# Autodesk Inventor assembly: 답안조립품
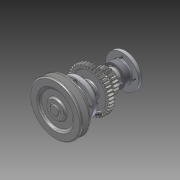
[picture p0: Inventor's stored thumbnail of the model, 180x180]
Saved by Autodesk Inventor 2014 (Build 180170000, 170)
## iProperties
Created: 2016-01
Part Number: 답안조립품
Document SubType Name: Assembly
Designer: SCD-A15
Author: SCD-A15
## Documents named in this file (16)
- C:\Users\SCD-A15\Desktop\460105V1033\답안조립품.iam
- C:\Users\SCD-A15\Desktop\460105V1033\V-벨트풀리.ipt
- C:\Users\SCD-A15\Desktop\460105V1033\뒤커버.ipt
- C:\Users\SCD-A15\Desktop\460105V1033\멈춤나사 - M4x10.ipt
- C:\Users\SCD-A15\Desktop\460105V1033\베어링 6203.ipt
- C:\Users\SCD-A15\Desktop\460105V1033\본체.ipt
- C:\Users\SCD-A15\Desktop\460105V1033\볼트 M3 x 8.ipt
- C:\Users\SCD-A15\Desktop\460105V1033\볼트 M3 x 10.ipt
- C:\Users\SCD-A15\Desktop\460105V1033\부시1.ipt
- C:\Users\SCD-A15\Desktop\460105V1033\부시2.ipt
- C:\Users\SCD-A15\Desktop\460105V1033\스퍼기어.ipt
- C:\Users\SCD-A15\Desktop\460105V1033\앞커버.ipt
- C:\Users\SCD-A15\Desktop\460105V1033\오일씰 28 40 8.ipt
- C:\Users\SCD-A15\Desktop\460105V1033\축.ipt
- C:\Users\SCD-A15\Desktop\460105V1033\키 - 5 x 5 x 18.ipt
- C:\Users\SCD-A15\Desktop\460105V1033\키 - 6 x 6 x 22.ipt
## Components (9 placed, 3 different names)
1. V-벨트풀리:1 — 각도:4
2. ISO 4762 M3 x 8:1
3. ISO 4762 M3 x 8:2
4. ISO 4762 M3 x 8:3
5. ISO 4762 M3 x 8:4
6. ISO 4762 M3 x 10:1
7. ISO 4762 M3 x 10:2
8. ISO 4762 M3 x 10:3
9. ISO 4762 M3 x 10:4
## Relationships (1: Angle 1)
- 각도:4 [Angle]: V-벨트풀리:1
